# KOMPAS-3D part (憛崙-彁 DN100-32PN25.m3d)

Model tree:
1. Объединить компоненты:1  (labels: СЕНС-ПР DN100/32PN25)

Referenced files in D:\Савин\!СЕНСОР\3D для заказчика\!Новый перечень\СЕНС-ПР(-ПУ) двухпроходные\СЕНС-ПР DN100_32PN25\: СЕНС-ПР DN100_32PN25.a3d
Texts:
  СЕНС-ПР DN100/32PN25
  Body Specification ( left align )
  Body Specificaton ( centered )
  Трубка  разделительная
